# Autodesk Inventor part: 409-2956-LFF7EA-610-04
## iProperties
Created: 2011-01
Part Number: 409-2956-LFF7EA-610-04
Cost Center: 0 lbmass
Material: A36 STEEL PLATE
Document SubType Name: Sheet Metal
Designer: S. Boerckel
Authority: 0 in^3
Mass: 507.159 g
Surface Area: 175.273 cm^2
Volume: 64.5241 cm^3
Density: 7.86 g/cm^3
Flat Pattern Width: 15.24 cm
Flat Pattern Length: 8.89 cm
Flat Pattern Area: 135.484 cm^2
Sheet Metal Rule: 3/8"Thk
Description: GUSSET
SaveDate: 2008-01-15
SaveTime: 10:24
FileName: Sheet Metal
Wide: =<Flat Pattern Width>cm
Length: =<Flat Pattern Length>cm
Thickness: 0.3750 in
SMR: =<Sheet Metal Rule> - <Material>
Author: S. Boerckel
Revision Number: 0
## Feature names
1. Plate1
